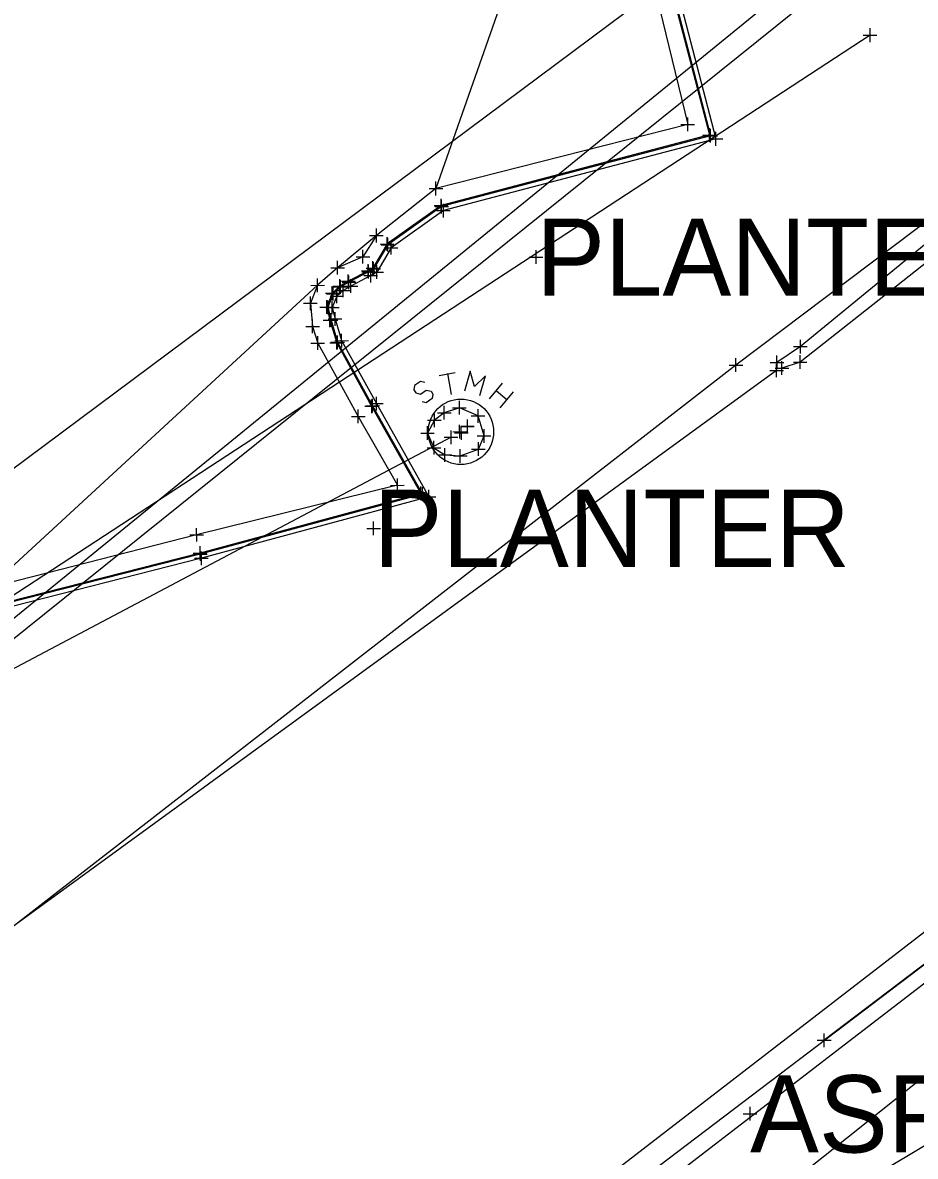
# Model space of a CAD drawing. Extents: x -1 to 1157254, y -1 to 2021979.
# Drawn here: x 1150149.9 to 1150233.1, y 2019513.5 to 2019619.2 of the extents above; entities that cross this region are included whole.
import ezdxf

# ---------------------------------------------------------------- set-up
doc = ezdxf.new("R2010")
doc.units = 0
for name, color, linetype in [('S_BUILDING_ANNOT', 7, 'Continuous'), ('S_CAL_CORNER_ANNOT', 7, 'Continuous'), ('S_CONTOUR_ANNOT', 7, 'Continuous'), ('S_CONTOUR_MINOR', 7, 'Continuous'), ('S_CTL_TABLE', 7, 'Continuous'), ('S_DITCHLINE', 7, 'Continuous'), ('S_DRIVEWAY_ANNOT', 7, 'Continuous'), ('S_DROP_INLET', 7, 'Continuous'), ('S_DROP_INLET_ANNOT', 7, 'Continuous'), ('S_EDGE_BITUMINOUS_ANNOT', 7, 'Continuous'), ('S_EDGE_PAVEMENT', 7, 'Continuous'), ('S_EDGE_PAVEMENT_ANNOT', 7, 'Continuous'), ('S_ELECTRIC_UTILITIES', 7, 'Continuous'), ('S_FENCE', 7, 'Continuous'), ('S_GAS_PUMP_ISLAND_ANNOT', 7, 'Continuous'), ('S_GATE', 7, 'Continuous')]:
    doc.layers.add(name, color=color, linetype=linetype)

msp = doc.modelspace()

# ---------------------------------------------------------------- linework, layer by layer
at = {"layer": 'S_BUILDING_ANNOT'}
for p, q in [((1150228.27, 2019618), (1150229.55, 2019618)), ((1150228.91, 2019617.36), (1150228.91, 2019618.64)), ((1150228.91, 2019618), (1150228.91, 2019618)), ((1150211.91, 2019609.06), (1150211.91, 2019610.33)), ((1150211.28, 2019609.69), (1150212.55, 2019609.69)), ((1150211.91, 2019609.69), (1150211.91, 2019609.69)), ((1150214.05, 2019607.99), (1150214.05, 2019609.26)), ((1150213.42, 2019608.62), (1150214.69, 2019608.63)), ((1150213.9, 2019608.34), (1150215.18, 2019608.34)), ((1150214.05, 2019608.62), (1150214.05, 2019608.62)), ((1150214.54, 2019607.7), (1150214.54, 2019608.98)), ((1150214.54, 2019608.34), (1150214.54, 2019608.34)), ((1150188.44, 2019603.07), (1150188.44, 2019604.35)), ((1150187.81, 2019603.71), (1150189.08, 2019603.71)), ((1150188.44, 2019603.71), (1150188.44, 2019603.71)), ((1150188.33, 2019602.02), (1150189.61, 2019602.02)), ((1150188.97, 2019601.38), (1150188.97, 2019602.66)), ((1150188.97, 2019602.02), (1150188.97, 2019602.02)), ((1150189.14, 2019601.01), (1150189.14, 2019602.29)), ((1150188.5, 2019601.65), (1150189.78, 2019601.65)), ((1150189.14, 2019601.65), (1150189.14, 2019601.65)), ((1150182.9, 2019598.69), (1150182.9, 2019599.97)), ((1150182.26, 2019599.33), (1150183.53, 2019599.33)), ((1150182.9, 2019599.33), (1150182.9, 2019599.33)), ((1150183.97, 2019597.83), (1150183.96, 2019599.1)), ((1150184.27, 2019597.55), (1150184.27, 2019598.83)), ((1150181.64, 2019596.71), (1150181.64, 2019597.99)), ((1150183.33, 2019598.47), (1150184.6, 2019598.47)), ((1150183.63, 2019598.19), (1150184.9, 2019598.19)), ((1150183.97, 2019598.47), (1150183.97, 2019598.47)), ((1150184.27, 2019598.19), (1150184.27, 2019598.19)), ((1150197.78, 2019596.68), (1150197.78, 2019597.95)), ((1150179.28, 2019595.69), (1150179.28, 2019596.96)), ((1150181, 2019597.35), (1150182.27, 2019597.35)), ((1150181.64, 2019597.35), (1150181.64, 2019597.35)), ((1150182.17, 2019595.31), (1150182.17, 2019596.58)), ((1150182.64, 2019595.57), (1150182.63, 2019596.84)), ((1150182.93, 2019595.28), (1150182.92, 2019596.55)), ((1150197.14, 2019597.31), (1150198.41, 2019597.32)), ((1150197.78, 2019597.31), (1150197.78, 2019597.31)), ((1150178.64, 2019596.32), (1150179.92, 2019596.32)), ((1150179.28, 2019596.32), (1150179.28, 2019596.32)), ((1150180.32, 2019594.34), (1150180.32, 2019595.61)), ((1150181.54, 2019595.95), (1150182.81, 2019595.95)), ((1150181.73, 2019595.6), (1150183, 2019595.6)), ((1150182, 2019596.21), (1150183.27, 2019596.21)), ((1150182.17, 2019595.95), (1150182.17, 2019595.95)), ((1150182.29, 2019595.91), (1150183.56, 2019595.91)), ((1150182.37, 2019594.96), (1150182.36, 2019596.23)), ((1150182.37, 2019595.6), (1150182.37, 2019595.6)), ((1150182.63, 2019596.21), (1150182.63, 2019596.21)), ((1150182.92, 2019595.91), (1150182.92, 2019595.91)), ((1150176.77, 2019594.68), (1150178.04, 2019594.69)), ((1150177.41, 2019594.05), (1150177.41, 2019595.32)), ((1150177.41, 2019594.69), (1150177.41, 2019594.69)), ((1150178.86, 2019593.26), (1150178.86, 2019594.53)), ((1150178.91, 2019594.53), (1150180.19, 2019594.54)), ((1150179.55, 2019593.9), (1150179.55, 2019595.17)), ((1150179.55, 2019594.53), (1150179.55, 2019594.53)), ((1150179.69, 2019594.97), (1150180.96, 2019594.97)), ((1150179.79, 2019593.57), (1150179.79, 2019594.85)), ((1150179.88, 2019594.62), (1150181.15, 2019594.62)), ((1150180.32, 2019594.97), (1150180.32, 2019594.97)), ((1150180.52, 2019593.99), (1150180.51, 2019595.26)), ((1150180.52, 2019594.62), (1150180.52, 2019594.62)), ((1150176.75, 2019592.37), (1150176.74, 2019593.64)), ((1150178.23, 2019593.9), (1150179.5, 2019593.9)), ((1150178.36, 2019592.01), (1150178.36, 2019593.28)), ((1150178.57, 2019593.66), (1150179.84, 2019593.67)), ((1150178.86, 2019593.9), (1150178.86, 2019593.9)), ((1150179.15, 2019594.21), (1150180.43, 2019594.21)), ((1150179.2, 2019593.03), (1150179.2, 2019594.3)), ((1150179.2, 2019593.66), (1150179.2, 2019593.66)), ((1150179.79, 2019594.21), (1150179.79, 2019594.21)), ((1150176.11, 2019593.01), (1150177.38, 2019593.01)), ((1150176.75, 2019593.01), (1150176.75, 2019593.01)), ((1150177.73, 2019592.65), (1150179, 2019592.65)), ((1150178.14, 2019592.62), (1150179.42, 2019592.62)), ((1150178.36, 2019592.65), (1150178.36, 2019592.65)), ((1150178.78, 2019591.98), (1150178.78, 2019593.25)), ((1150178.78, 2019592.62), (1150178.78, 2019592.62)), ((1150176.95, 2019590.22), (1150176.94, 2019591.49)), ((1150178.02, 2019591.45), (1150179.3, 2019591.45)), ((1150178.41, 2019591.55), (1150179.68, 2019591.55)), ((1150178.66, 2019590.81), (1150178.66, 2019592.08)), ((1150178.66, 2019591.45), (1150178.66, 2019591.45)), ((1150179.05, 2019590.92), (1150179.04, 2019592.19)), ((1150179.05, 2019591.55), (1150179.05, 2019591.55)), ((1150176.31, 2019590.85), (1150177.58, 2019590.85)), ((1150176.94, 2019590.85), (1150176.94, 2019590.85)), ((1150179.66, 2019588.89), (1150179.65, 2019590.16)), ((1150176.78, 2019589.29), (1150178.05, 2019589.29)), ((1150177.42, 2019588.66), (1150177.42, 2019589.93)), ((1150177.42, 2019589.29), (1150177.42, 2019589.29)), ((1150178.65, 2019589.37), (1150179.92, 2019589.37)), ((1150179.02, 2019589.52), (1150180.29, 2019589.53)), ((1150179.28, 2019588.73), (1150179.28, 2019590.01)), ((1150179.28, 2019589.37), (1150179.28, 2019589.37)), ((1150179.65, 2019589.53), (1150179.65, 2019589.53)), ((1150222.42, 2019588.33), (1150222.42, 2019589.61)), ((1150220.24, 2019586.86), (1150220.23, 2019588.13)), ((1150221.78, 2019588.97), (1150223.06, 2019588.97)), ((1150222.39, 2019586.9), (1150222.39, 2019588.17)), ((1150222.42, 2019588.97), (1150222.42, 2019588.97)), ((1150215.78, 2019587.25), (1150217.05, 2019587.25)), ((1150216.41, 2019586.62), (1150216.41, 2019587.89)), ((1150216.41, 2019587.25), (1150216.41, 2019587.25)), ((1150219.6, 2019587.49), (1150220.87, 2019587.49)), ((1150220.06, 2019586.96), (1150221.33, 2019586.96)), ((1150220.2, 2019586.11), (1150220.2, 2019587.38)), ((1150220.23, 2019587.49), (1150220.23, 2019587.49)), ((1150220.7, 2019586.33), (1150220.69, 2019587.6)), ((1150220.7, 2019586.96), (1150220.7, 2019586.96)), ((1150221.76, 2019587.53), (1150223.03, 2019587.53)), ((1150222.39, 2019587.53), (1150222.39, 2019587.53)), ((1150219.56, 2019586.75), (1150220.84, 2019586.75)), ((1150220.2, 2019586.75), (1150220.2, 2019586.75)), ((1150182.54, 2019582.83), (1150182.54, 2019584.1)), ((1150182.89, 2019583.02), (1150182.89, 2019584.29)), ((1150190.64, 2019582.64), (1150190.63, 2019583.91)), ((1150181.2, 2019581.83), (1150181.19, 2019583.11)), ((1150181.91, 2019583.46), (1150183.18, 2019583.47)), ((1150182.25, 2019583.66), (1150183.53, 2019583.66)), ((1150182.54, 2019583.46), (1150182.54, 2019583.46)), ((1150182.89, 2019583.66), (1150182.89, 2019583.66)), ((1150188.31, 2019581.47), (1150188.31, 2019582.74)), ((1150188.58, 2019582.81), (1150189.86, 2019582.81)), ((1150189.22, 2019582.17), (1150189.22, 2019583.44)), ((1150189.22, 2019582.81), (1150189.22, 2019582.81)), ((1150190, 2019583.27), (1150191.27, 2019583.27)), ((1150190.63, 2019583.27), (1150190.63, 2019583.27)), ((1150192.38, 2019581.88), (1150192.37, 2019583.15)), ((1150180.56, 2019582.47), (1150181.83, 2019582.47)), ((1150181.19, 2019582.47), (1150181.19, 2019582.47)), ((1150187.67, 2019582.1), (1150188.94, 2019582.11)), ((1150188.31, 2019582.1), (1150188.31, 2019582.1)), ((1150190.66, 2019580.41), (1150190.65, 2019581.68)), ((1150191.38, 2019580.9), (1150191.38, 2019582.18)), ((1150191.39, 2019580.89), (1150191.38, 2019582.17)), ((1150191.74, 2019582.51), (1150193.01, 2019582.52)), ((1150192.38, 2019582.51), (1150192.38, 2019582.51)), ((1150187.02, 2019580.9), (1150188.29, 2019580.9)), ((1150187.65, 2019580.27), (1150187.65, 2019581.54)), ((1150187.65, 2019580.9), (1150187.65, 2019580.9)), ((1150189.85, 2019579.89), (1150189.85, 2019581.16)), ((1150190.02, 2019581.04), (1150191.29, 2019581.05)), ((1150190.17, 2019580.92), (1150191.44, 2019580.92)), ((1150190.65, 2019581.05), (1150190.65, 2019581.05)), ((1150190.75, 2019581.54), (1150192.02, 2019581.54)), ((1150190.75, 2019581.53), (1150192.02, 2019581.53)), ((1150190.81, 2019580.28), (1150190.8, 2019581.56)), ((1150190.81, 2019580.92), (1150190.81, 2019580.92)), ((1150191.38, 2019581.54), (1150191.38, 2019581.54)), ((1150191.38, 2019581.53), (1150191.38, 2019581.53)), ((1150192.29, 2019580.64), (1150193.56, 2019580.64)), ((1150192.93, 2019580.01), (1150192.93, 2019581.28)), ((1150192.93, 2019580.64), (1150192.93, 2019580.64)), ((1150187.63, 2019579.54), (1150188.9, 2019579.55)), ((1150188.27, 2019578.91), (1150188.26, 2019580.18)), ((1150188.26, 2019579.54), (1150188.26, 2019579.54)), ((1150189.21, 2019580.52), (1150190.49, 2019580.52)), ((1150189.85, 2019580.52), (1150189.85, 2019580.52)), ((1150192.4, 2019578.79), (1150192.4, 2019580.06)), ((1150188.63, 2019578.87), (1150189.91, 2019578.87)), ((1150189.27, 2019578.23), (1150189.27, 2019579.51)), ((1150189.27, 2019578.87), (1150189.27, 2019578.87)), ((1150190.08, 2019578.78), (1150191.35, 2019578.78)), ((1150190.71, 2019578.14), (1150190.71, 2019579.42)), ((1150190.71, 2019578.78), (1150190.71, 2019578.78)), ((1150191.76, 2019579.42), (1150193.03, 2019579.42)), ((1150192.4, 2019579.42), (1150192.4, 2019579.42)), ((1150184.85, 2019575.4), (1150184.85, 2019576.67)), ((1150184.21, 2019576.03), (1150185.49, 2019576.04)), ((1150184.85, 2019576.04), (1150184.85, 2019576.04)), ((1150187.18, 2019574.59), (1150187.18, 2019575.87)), ((1150187.79, 2019574.34), (1150187.78, 2019575.62)), ((1150186.55, 2019575.23), (1150187.82, 2019575.23)), ((1150187.15, 2019574.98), (1150188.42, 2019574.98)), ((1150187.18, 2019575.23), (1150187.18, 2019575.23)), ((1150187.78, 2019574.98), (1150187.78, 2019574.98)), ((1150182.63, 2019571.39), (1150182.63, 2019572.66)), ((1150165.5, 2019571.42), (1150166.77, 2019571.43)), ((1150166.14, 2019570.79), (1150166.13, 2019572.06)), ((1150166.13, 2019571.42), (1150166.13, 2019571.42)), ((1150182, 2019572.03), (1150183.27, 2019572.03)), ((1150182.63, 2019572.03), (1150182.63, 2019572.03)), ((1150166.48, 2019568.99), (1150166.47, 2019570.26)), ((1150165.84, 2019569.62), (1150167.11, 2019569.63)), ((1150165.94, 2019569.24), (1150167.21, 2019569.24)), ((1150166.47, 2019569.63), (1150166.47, 2019569.63)), ((1150166.58, 2019568.6), (1150166.58, 2019569.87)), ((1150166.58, 2019569.24), (1150166.58, 2019569.24)), ((1150217.08, 2019517.45), (1150218.36, 2019517.46)), ((1150217.72, 2019516.82), (1150217.72, 2019518.09)), ((1150217.72, 2019517.45), (1150217.72, 2019517.45))]:
    msp.add_line(p, q, dxfattribs=at)
at = {"layer": 'S_CAL_CORNER_ANNOT'}
msp.add_lwpolyline([(1150682.05, 2019865.85), (1150601.54, 2019813.47), (1150510.58, 2019743.97), (1150405.28, 2019665.92), (1150310.69, 2019593.56), (1150188.92, 2019499.64), (1150039.45, 2019388.15), (1149962.15, 2019331.17), (1149944.63, 2019319.08), (1149774.15, 2019191.52), (1149712.73, 2019145.6), (1149665.81, 2019108.74), (1149605.46, 2019057.66), (1149527.46, 2018983.58), (1149450.12, 2018902.93), (1149278.32, 2018738.82), (1149257.2, 2018716.38), (1149237.23, 2018691.25), (1149165.09, 2018617.77), (1149125.26, 2018579.57), (1149069.5, 2018523.84), (1149012.03, 2018473.77), (1148938.88, 2018408.55)], dxfattribs=at)
at = {"layer": 'S_CONTOUR_ANNOT'}
for points in [[(1150857.08, 2020031.73), (1150832.22, 2020016.43), (1150747.37, 2019963.08), (1150692.94, 2019929.63), (1150639.49, 2019893), (1150583.9, 2019856.96), (1150484.25, 2019790.85), (1150433.08, 2019750.74), (1150355.8, 2019695.65), (1150341.28, 2019681.73), (1150287.94, 2019641.18), (1150216.41, 2019587.25), (1150034.4, 2019445.88), (1149979.98, 2019405.6), (1149934.92, 2019374.11), (1149784.56, 2019258.12)], [(1150776.08, 2020000.06), (1150711.77, 2019956.26), (1150627.27, 2019900.66), (1150578.77, 2019864.96), (1150479.12, 2019798.68), (1150423.47, 2019764.16), (1150358.5, 2019722.73), (1150313.96, 2019690.01), (1150273.95, 2019661.03), (1150225.64, 2019623.26), (1150033.5, 2019468.9), (1149971.69, 2019423.78), (1149931.59, 2019393.98), (1149688.42, 2019230.92)]]:
    msp.add_lwpolyline(points, dxfattribs=at)
at = {"layer": 'S_CONTOUR_MINOR'}
msp.add_lwpolyline([(1150216.08, 2019627.58), (1149895.48, 2019388.62)], dxfattribs=at)
at = {"layer": 'S_CTL_TABLE'}
for p, q in [((1150213.93, 2019608.06), (1150213.93, 2019609.33)), ((1150213.29, 2019608.69), (1150214.57, 2019608.7)), ((1150213.93, 2019608.7), (1150213.93, 2019608.7)), ((1150188.29, 2019602.11), (1150189.56, 2019602.11)), ((1150188.93, 2019601.47), (1150188.92, 2019602.75)), ((1150188.93, 2019602.11), (1150188.93, 2019602.11)), ((1150183.89, 2019597.9), (1150183.89, 2019599.17)), ((1150183.25, 2019598.53), (1150184.53, 2019598.54)), ((1150183.89, 2019598.54), (1150183.89, 2019598.54)), ((1150182.13, 2019595.4), (1150182.12, 2019596.67)), ((1150182.56, 2019595.65), (1150182.56, 2019596.92)), ((1150180.28, 2019594.43), (1150180.27, 2019595.7)), ((1150181.49, 2019596.03), (1150182.76, 2019596.04)), ((1150181.93, 2019596.28), (1150183.2, 2019596.28)), ((1150182.13, 2019596.04), (1150182.13, 2019596.04)), ((1150182.56, 2019596.28), (1150182.56, 2019596.28)), ((1150178.78, 2019593.32), (1150178.78, 2019594.59)), ((1150178.86, 2019594.61), (1150180.13, 2019594.62)), ((1150179.49, 2019593.98), (1150179.49, 2019595.25)), ((1150179.49, 2019594.62), (1150179.49, 2019594.62)), ((1150179.64, 2019595.06), (1150180.91, 2019595.06)), ((1150180.28, 2019595.06), (1150180.28, 2019595.06)), ((1150178.14, 2019593.95), (1150179.42, 2019593.96)), ((1150178.26, 2019592.02), (1150178.26, 2019593.29)), ((1150178.78, 2019593.95), (1150178.78, 2019593.95)), ((1150177.62, 2019592.65), (1150178.89, 2019592.65)), ((1150178.26, 2019592.65), (1150178.26, 2019592.65)), ((1150177.93, 2019591.42), (1150179.2, 2019591.42)), ((1150178.56, 2019590.78), (1150178.56, 2019592.06)), ((1150178.56, 2019591.42), (1150178.56, 2019591.42)), ((1150178.56, 2019589.33), (1150179.83, 2019589.33)), ((1150179.19, 2019588.69), (1150179.19, 2019589.97)), ((1150179.19, 2019589.33), (1150179.19, 2019589.33)), ((1150182.46, 2019582.78), (1150182.45, 2019584.05)), ((1150181.82, 2019583.41), (1150183.09, 2019583.42)), ((1150182.45, 2019583.42), (1150182.45, 2019583.42)), ((1150187.03, 2019574.66), (1150187.03, 2019575.93)), ((1150186.4, 2019575.29), (1150187.67, 2019575.29)), ((1150187.03, 2019575.29), (1150187.03, 2019575.29)), ((1150166.45, 2019569.09), (1150166.45, 2019570.36)), ((1150165.81, 2019569.72), (1150167.09, 2019569.72)), ((1150166.45, 2019569.72), (1150166.45, 2019569.72)), ((1150224.63, 2019523.68), (1150224.63, 2019524.95)), ((1150223.99, 2019524.31), (1150225.27, 2019524.32)), ((1150224.63, 2019524.31), (1150224.63, 2019524.31))]:
    msp.add_line(p, q, dxfattribs=at)
at = {"layer": 'S_DITCHLINE'}
for p, q in [((1150188.73, 2019586.29), (1150190.24, 2019586.57)), ((1150189.51, 2019586.45), (1150189.86, 2019584.51)), ((1150186.45, 2019585.33), (1150186.37, 2019584.94)), ((1150186.37, 2019584.94), (1150186.57, 2019584.67)), ((1150186.99, 2019585.71), (1150186.45, 2019585.33)), ((1150187.42, 2019585.64), (1150186.99, 2019585.71)), ((1150186.99, 2019584.55), (1150187.53, 2019584.9)), ((1150187.53, 2019584.9), (1150188, 2019584.82)), ((1150193.42, 2019584.09), (1150194.66, 2019585.56)), ((1150194.08, 2019584.86), (1150195.05, 2019584.05)), ((1150186.57, 2019584.67), (1150186.99, 2019584.55)), ((1150187.53, 2019583.74), (1150187.15, 2019583.82)), ((1150188.08, 2019584.13), (1150187.53, 2019583.74)), ((1150188, 2019584.82), (1150188.15, 2019584.55)), ((1150188.15, 2019584.55), (1150188.08, 2019584.13)), ((1150195.63, 2019584.75), (1150194.39, 2019583.27))]:
    msp.add_line(p, q, dxfattribs=at)
for points in [[(1150228.91, 2019618), (1150099.15, 2019533.18)], [(1150340.68, 2019612.36), (1149611.97, 2019059.3)], [(1150192.53, 2019584.4), (1150193.07, 2019586.26), (1150192.03, 2019585.25), (1150191.64, 2019586.68), (1150191.1, 2019584.82)]]:
    msp.add_lwpolyline(points, dxfattribs=at)
msp.add_circle((1150190.77, 2019581.03), 3.05, dxfattribs=at)
at = {"layer": 'S_DRIVEWAY_ANNOT'}
for points in [[(1150349.55, 2019719.95), (1150349.48, 2019718.28), (1150346.68, 2019700.41), (1150344.79, 2019694.4), (1150310.73, 2019658.1), (1150274.35, 2019629.73), (1150247.23, 2019609.31), (1150222.42, 2019588.97), (1150220.23, 2019587.49)], [(1150350.63, 2019719.89), (1150351.06, 2019717.32), (1150349.29, 2019696.61), (1150349.96, 2019695.5), (1150349.55, 2019693.99), (1150348.12, 2019692.84), (1150312.16, 2019656.07), (1150275.89, 2019627.69), (1150248.31, 2019607.96), (1150222.39, 2019587.53), (1150220.7, 2019586.96)]]:
    msp.add_lwpolyline(points, dxfattribs=at)
at = {"layer": 'S_DROP_INLET'}
for points in [[(1150852.18, 2019973.05), (1150778.54, 2019928.45), (1150770.16, 2019919.18), (1150703.8, 2019877.29), (1150608.63, 2019809.12), (1150513.43, 2019739.89), (1150405.92, 2019663.65), (1150352.2, 2019622.72), (1150343.81, 2019614.74), (1150336.72, 2019606.98), (1150314.89, 2019591.84), (1150193.25, 2019498.28), (1150112.69, 2019435.49), (1150059.59, 2019406.16), (1150037.88, 2019389.79), (1149962.99, 2019329.91), (1149914.05, 2019297.4), (1149863.26, 2019256.98)], [(1150343.79, 2019722.31), (1149825.67, 2019300.1)]]:
    msp.add_lwpolyline(points, dxfattribs=at)
at = {"layer": 'S_DROP_INLET_ANNOT'}
for points in [[(1150220.2, 2019586.75), (1150114.25, 2019509.61)], [(1150191.38, 2019581.53), (1150191.38, 2019581.54)], [(1150189.85, 2019580.52), (1150098.63, 2019532.28)]]:
    msp.add_lwpolyline(points, dxfattribs=at)
at = {"layer": 'S_EDGE_BITUMINOUS_ANNOT'}
for points in [[(1150191.93, 2019694.57), (1150199.54, 2019665.18), (1150209.32, 2019626.4), (1150213.93, 2019608.7), (1150188.93, 2019602.11), (1150183.89, 2019598.54), (1150182.56, 2019596.28), (1150182.13, 2019596.04), (1150180.28, 2019595.06), (1150179.49, 2019594.62), (1150178.78, 2019593.95), (1150178.26, 2019592.65), (1150178.56, 2019591.42), (1150179.19, 2019589.33), (1150182.45, 2019583.42), (1150187.03, 2019575.29), (1150166.45, 2019569.72), (1150135.63, 2019561.88), (1150107.22, 2019554.65)], [(1150343.65, 2019608.8), (1150321.84, 2019595.44), (1150270.77, 2019549.67), (1150236.43, 2019533.28), (1150224.63, 2019524.31)], [(1150346.72, 2019587.58), (1150319.73, 2019580.37), (1150276.31, 2019529.58), (1150250.87, 2019524.53), (1150230.87, 2019512.6)]]:
    msp.add_lwpolyline(points, dxfattribs=at)
at = {"layer": 'S_EDGE_PAVEMENT'}
for points in [[(1150192.03, 2019694.6), (1150199.64, 2019665.2), (1150209.42, 2019626.42), (1150214.05, 2019608.62), (1150188.97, 2019602.02), (1150183.97, 2019598.47), (1150182.63, 2019596.21), (1150182.17, 2019595.95), (1150180.32, 2019594.97), (1150179.55, 2019594.53), (1150178.86, 2019593.9), (1150178.36, 2019592.65), (1150178.66, 2019591.45), (1150179.28, 2019589.37), (1150182.54, 2019583.46), (1150187.18, 2019575.23), (1150166.47, 2019569.63), (1150135.65, 2019561.78), (1150107.24, 2019554.55)], [(1150192.42, 2019694.7), (1150200.02, 2019665.3), (1150209.81, 2019626.52), (1150214.54, 2019608.34), (1150189.14, 2019601.65), (1150184.27, 2019598.19), (1150182.92, 2019595.91), (1150182.37, 2019595.6), (1150180.52, 2019594.62), (1150179.79, 2019594.21), (1150179.2, 2019593.66), (1150178.78, 2019592.62), (1150179.05, 2019591.55), (1150179.65, 2019589.53), (1150182.89, 2019583.66), (1150187.78, 2019574.98), (1150166.58, 2019569.24), (1150135.75, 2019561.4), (1150107.34, 2019554.17)]]:
    msp.add_lwpolyline(points, dxfattribs=at)
at = {"layer": 'S_EDGE_PAVEMENT_ANNOT'}
msp.add_lwpolyline([(1150207.82, 2019626.54), (1150211.91, 2019609.69), (1150188.44, 2019603.71), (1150182.9, 2019599.33), (1150181.64, 2019597.35), (1150179.28, 2019596.32), (1150177.41, 2019594.69), (1150176.75, 2019593.01), (1150176.94, 2019590.85), (1150177.42, 2019589.29), (1150181.19, 2019582.47), (1150184.85, 2019576.04), (1150166.13, 2019571.42), (1150135.51, 2019563.6)], dxfattribs=at)
at = {"layer": 'S_ELECTRIC_UTILITIES'}
msp.add_lwpolyline([(1150190.71, 2019578.78), (1150192.4, 2019579.42), (1150192.93, 2019580.64), (1150192.38, 2019582.51), (1150190.63, 2019583.27), (1150189.22, 2019582.81), (1150188.31, 2019582.1), (1150187.65, 2019580.9), (1150188.26, 2019579.54), (1150189.27, 2019578.87)], close=True, dxfattribs=at)
at = {"layer": 'S_FENCE'}
msp.add_lwpolyline([(1150775.16, 2019913.88), (1150697.15, 2019862.05), (1150611.54, 2019805.47), (1150516.86, 2019735.37), (1150402.98, 2019659.79), (1150352.98, 2019622.15), (1150350.25, 2019606.72), (1150331.34, 2019598.55), (1150196.24, 2019490.87), (1150043.62, 2019380.11), (1149966.77, 2019324.72), (1149934.21, 2019308.48), (1149916.33, 2019289.12), (1149866.68, 2019250.91)], dxfattribs=at)
at = {"layer": 'S_GAS_PUMP_ISLAND_ANNOT'}
msp.add_lwpolyline([(1150203.02, 2019645.3), (1150188.44, 2019603.71), (1150182.9, 2019599.33), (1150179.28, 2019596.32), (1150177.41, 2019594.69), (1150146.76, 2019566.47), (1150137.07, 2019564), (1150135.51, 2019563.6), (1150125.84, 2019561.05), (1150076.81, 2019565.5), (1150075.76, 2019565.92), (1150074.06, 2019565.41), (1150073.45, 2019564.81), (1150072.29, 2019563.24), (1150073.79, 2019556.16), (1150076.59, 2019546.57), (1150077.95, 2019541.9), (1150050.36, 2019502.19)], dxfattribs=at)

# ---------------------------------------------------------------- texts
at = {"layer": 'S_GATE'}
for s, p in [('PLANTER', (1150197.78, 2019593.71)), ('PLANTER', (1150182.63, 2019568.43)), ('ASPH DW', (1150217.72, 2019513.85))]:
    msp.add_text(s, height=7.2, dxfattribs=at).set_placement(p)

doc.saveas('drawing.dxf')
